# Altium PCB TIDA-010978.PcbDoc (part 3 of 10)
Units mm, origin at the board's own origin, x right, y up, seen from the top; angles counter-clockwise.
Board outline 243.95 x 94.85 mm, 4 copper layers (Top Layer, Mid Layer 1, Mid Layer 2, Bottom Layer), stack 1.623 mm thick; 865 components, 374 nets, 2308 pads, 2132 vias.
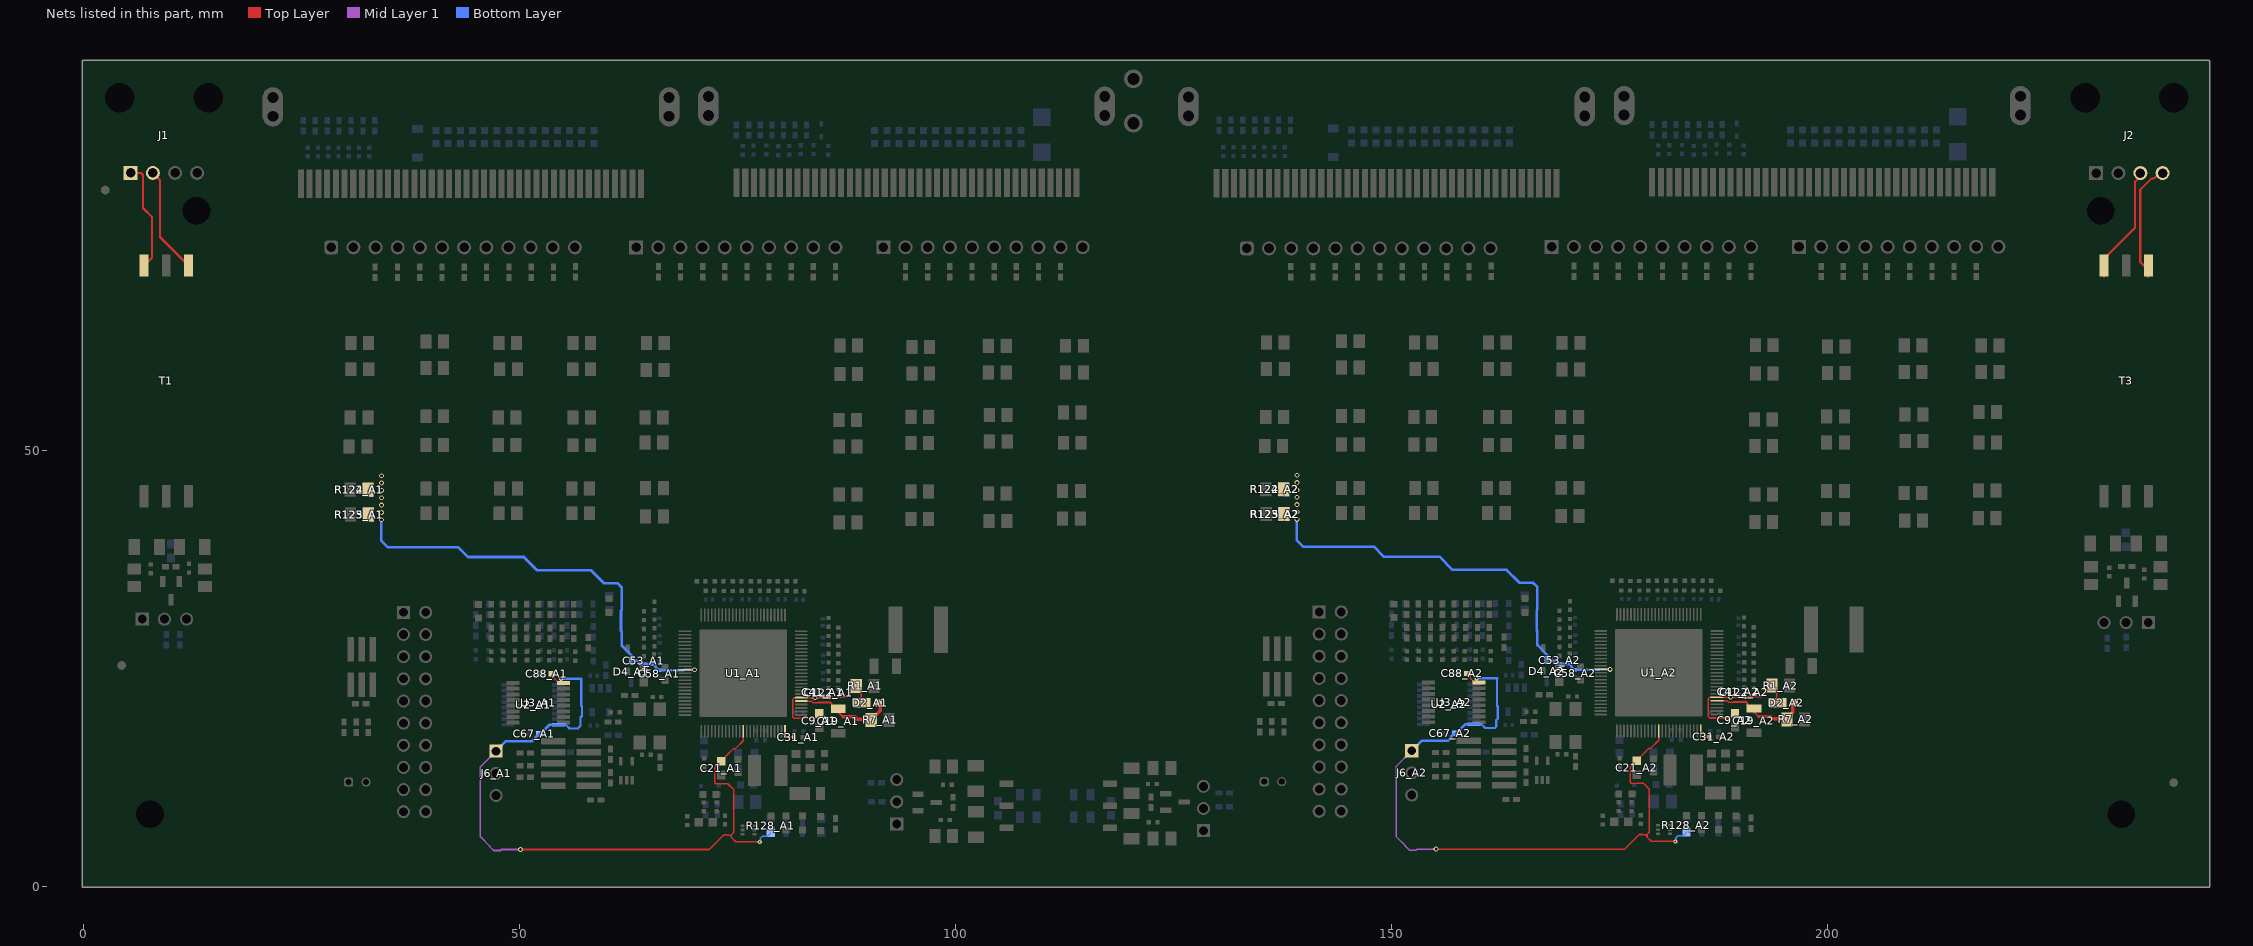
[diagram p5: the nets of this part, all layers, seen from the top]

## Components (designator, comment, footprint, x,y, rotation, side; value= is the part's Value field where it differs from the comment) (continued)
T2 "74941301" FP-HMU1228NL_SMT_TRANSFORMER_8MM89_10MM09-MFG 111.8,9.242 r0 top
T3 "LKBMT10B" FP-LKBMT10B_SMT_XFRMR_27MM9_12MM5-MFG 234.256,57.975 r270 top
TSREF_LED1_A1 "150060GS75000" WL-SMCW_GREEN 60.292,32.184 r270 top value=Green (schematic designator TSREF_LED1)
TSREF_LED1_A2 "150060GS75000" WL-SMCW_GREEN 165.293,32.234 r270 top value=Green (schematic designator TSREF_LED1)
U1_A1 "BQ79826ZQPZSRQ1" PZQ0100A-MFG 75.657,24.449 r180 top (schematic designator U1)
U1_A2 "BQ79826ZQPZSRQ1" PZQ0100A-MFG 180.657,24.499 r180 top (schematic designator U1)
U2_A1 "TMUX1308PWR" PW0016A-MFG 51.573,20.814 r0 bottom (schematic designator U2)
U2_A2 "TMUX1308PWR" PW0016A-MFG 156.573,20.864 r0 bottom (schematic designator U2)
U3_A1 "TMUX1308PWR" PW0016A-MFG 52.143,21.049 r0 top (schematic designator U3)
U3_A2 "TMUX1308PWR" PW0016A-MFG 157.143,21.099 r0 top (schematic designator U3)
U4_A1 "TLV74315PDBVR" DBV0005A_N 59.3,21.342 r270 bottom (schematic designator U4)
U4_A2 "TLV74315PDBVR" DBV0005A_N 164.3,21.392 r270 bottom (schematic designator U4)
U5_A1 "SN74LXC1T14DCKR" DCK0005A-MFG 62.287,13.257 r90 top (schematic designator U5)
U5_A2 "SN74LXC1T14DCKR" DCK0005A-MFG 167.287,13.307 r90 top (schematic designator U5)
Y2_A1 "830055663" FP-830055663_SMT_CRYSTAL_5MM0_3MM2-MFG 64.944,18.413 r90 top (schematic designator Y2)
Y2_A2 "830055663" FP-830055663_SMT_CRYSTAL_5MM0_3MM2-MFG 169.944,18.463 r90 top (schematic designator Y2)
ZZ1 "This Assembly Note is for PCB labels only" AssemblyNoteLabel 32.749,188.65 r0 top
ZZ2 "These assemblies are ESD sensitive, ESD precautions shall be observed." AssemblyNote 32.749,185.884 r0 top
ZZ3 "These assemblies must be clean and free from flux and all contaminants. Use of no clean flux is not acceptable." AssemblyNote 32.749,183.635 r0 top
ZZ4 "These assemblies must comply with workmanship standards IPC-A-610 Class 2, unless otherwise specified." AssemblyNote 32.749,181.386 r0 top

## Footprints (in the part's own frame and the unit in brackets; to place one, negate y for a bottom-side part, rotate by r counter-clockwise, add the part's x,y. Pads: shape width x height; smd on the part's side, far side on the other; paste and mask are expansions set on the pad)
0402 [mm] "0402 from SM-752 data"
  rect 0.8x0.6 smd: 1(-0.6,0) 2(0.6,0)
  silkscreen extent -1.22,-0.52 1.22,0.52, body extent -0.55,-0.3 0.55,0.3, height 0.6
0603 [mm] "0603 from SM-752 data"
  rect 1x0.95 smd: 1(-0.8,0) 2(0.8,0)
  silkscreen extent -1.52,-0.69 1.52,0.69, body extent -0.87,-0.47 0.87,0.47, height 1
0805_HV [mil] "0805 with 30mil clearance between pads"
  rect 50x63 smd: 1(-40,0) 2(40,0)
  silkscreen extent -74,-40 74,40, body extent -43,-29 43,29, height 57
1206 [mm] "1206 from SM-752 data"
  rect 1.3x1.85 smd: 1(-1.45,0) 2(1.45,0)
  silkscreen extent -2.4,-1.21 2.4,1.21, body extent -1.7,-0.9 1.7,0.9, height 1.35
2220_280 [mm] "Chip Capacitor, Body 5.7x5.0mm, IPC Medium Density"
  rect 1.6x5.3 smd: 1(-2.6,0) 2(2.6,0)
  silkscreen extent -3.69,-2.94 3.69,2.94, body extent -2.95,-2.62 2.95,2.62, height 2.8
61301211121 [mm] "Pin Header, pitch 2.54 mm, THT, Vertical, single row, 12p"
  rrect50% 1.6x1.6 hole 1.1: 1(-13.97,0)
  round 1.6 hole 1.1: 2(-11.43,0) 3(-8.89,0) 4(-6.35,0) 5(-3.81,0) 6(-1.27,0) 7(1.27,0) 8(3.81,0) 9(6.35,0) 10(8.89,0) 11(11.43,0) 12(13.97,0)
  silkscreen extent -15.96,-1.35 15.39,1.35, body extent -15.24,-1.27 15.24,1.27, height 8.57
AssemblyNote [mm] "Assembly Note"
AssemblyNoteLabel [mm] "Assembly Note for PCB Labels"
CE_Mark_5mm [mm] "Minimum text height for CE Mark"
  silkscreen extent -3.5,-2.5 3.5,2.5
CONN_PEC03SAAN [mm] "SULLINS"
  rect 1.5x1.5 hole 1.016: 1(-2.54,0)
  round 1.5 hole 1.016: 2(0,0) 3(2.54,0)
  silkscreen extent -4.72,-1.27 3.81,1.27, body extent -3.84,-1.3 3.84,1.3, height 8.38
DBV0005A_N [mm] "SOT23, 5-Leads, Body 2.9x1.6mm, Pitch 0.95mm, Lead Span 2.8mm, IPC Medium Density"
  rrect17% 1x0.6 smd: 1(-1.375,0.95) 2(-1.375,0) 3(-1.375,-0.95) 4(1.375,-0.95) 5(1.375,0.95)
  silkscreen extent -0.25,-1.55 0.25,1.55, body extent -1.42,-1.46 1.42,1.46, height 1.09
DBZ0003A-MFG [mm]
  rrect17% 1.3x0.6 smd paste+0 mask+0: 1(-1.05,0.95) 2(-1.05,-0.95) 3(1.05,0)
  silkscreen extent -0.03,-1.52 0.7,1.52, body extent -1.8,-1.62 1.8,1.62, height 0.25
DCK0005A-MFG [mm]
  rrect25% 0.95x0.4 smd paste+0 mask+0: 1(-1.1,0.65) 2(-1.1,0) 3(-1.1,-0.65) 4(1.1,-0.65) 5(1.1,0.65)
  silkscreen extent -2.25,-1.07 0.23,1.07, body extent -1.68,-1.17 1.68,1.17, height 0.25
DYA0002A-MFG [mm]
  rrect25% 0.67x0.4 smd paste+0 mask+0: 1(-0.74,0) 2(0.74,0)
  silkscreen extent -1.75,-0.63 0.65,0.63, body extent -0.8,-0.39 0.8,0.39, height 0.77
DYF0002A-MFG [mm] "Recommended Land Pattern"
  rrect20% 0.9x0.5 smd paste+0 mask+0: 1(-1.3,0) 2(1.3,0)
  silkscreen extent -1.55,-0.7 0.9,0.92, body extent -1.33,-0.65 1.33,0.65, height 1
FCC_disclaimer [mm]
Fiducial10-20 [mm]
  round 1 smd mask+0.5: 1(0,0)
  Top Layer keep-out circle w1.178: c0,0 r0.5
FP-63824-1_CONN_7MM92_3MM11-MFG [mm]
  round 2.15 hole 1.4 paste-2539.97 mask+0: 1(-2.54,0) 1(2.54,0)
  silkscreen extent -4.09,-1.56 4.09,1.56, body extent -3.96,-1.54 3.96,1.54, height 10.88
FP-141114-214010_HDR40-MFG [mm]
  rrect14% 0.7x3.3 smd paste+0 mask+0: 1(18.5,7.7) 2(16.5,7.7) 3(14.5,7.7) 4(12.5,7.7) 5(10.5,7.7) 6(8.5,7.7) 7(6.5,7.7) 8(4.5,7.7) 9(2.5,7.7) 10(0.5,7.7) 11(-1.5,7.7) 12(-3.5,7.7) 13(-5.5,7.7) 14(-7.5,7.7) 15(-9.5,7.7) 16(-11.5,7.7) 17(-13.5,7.7) 18(-15.5,7.7) 19(-17.5,7.7) 20(-19.5,7.7) 21(19.5,7.7) 22(17.5,7.7) 23(15.5,7.7) 24(13.5,7.7) 25(11.5,7.7) 26(9.5,7.7) 27(7.5,7.7) 28(5.5,7.7) 29(3.5,7.7) 30(1.5,7.7) 31(-0.5,7.7) 32(-2.5,7.7) 33(-4.5,7.7) 34(-6.5,7.7) 35(-8.5,7.7) 36(-10.5,7.7) 37(-12.5,7.7) 38(-14.5,7.7) 39(-16.5,7.7) 40(-18.5,7.7)
  round 2.35 hole 1.25 paste-2539.97 mask+0: 41(-22.725,-2.175) 41(-22.725,-0.025) 42(22.725,-2.175) 42(22.725,-0.025)
  rrect100% 2.35x4.5 smd paste+0 mask+0: 41(-22.725,-1.1) 42(22.725,-1.1)
  rrect100% 2.35x4.5 smd far side paste+0 mask+0: 41(-22.725,-1.1) 42(22.725,-1.1)
  silkscreen extent -23.95,1.83 23.95,10.02, body extent -24.05,-9.3 24.05,9.45, height 0.25
FP-830055663_SMT_CRYSTAL_5MM0_3MM2-MFG [mm]
  rrect7% 1.6x1.4 smd paste+0 mask+0: 1(-1.9,-1.15) 2(1.9,-1.15) 3(1.9,1.15) 4(-1.9,1.15)
  silkscreen extent -2.55,-2.53 2.55,1.65, body extent -2.5,-1.6 2.5,1.6, height 1
FP-885012206050_0603-MFG [mm]
  rrect13% 0.8x0.8 smd paste+0 mask+0: 1(-0.75,0) 2(0.75,0)
  silkscreen extent -0.85,-0.77 0.85,0.77, body extent -0.8,-0.4 0.8,0.4, height 0.87
FP-C1206C-EB-MFG [mm]
  rect 0.95x1.7 smd paste+0 mask+0: 1(-1.4,0) 2(1.4,0)
  silkscreen extent -0.55,-0.9 0.55,0.9, body extent -2,-1 2,1, height 0.25
FP-CRCW120662R0JNEAHP_1206-MFG [mm] "Recommended Land Pattern"
  rrect10% 1.05x1.8 smd paste+0 mask+0: 1(-1.275,0) 2(1.275,0)
  silkscreen extent -0.38,-0.87 0.38,0.87, body extent -1.55,-0.8 1.55,0.8, height 0.65
FP-DFLS1200Q-7_PowerDI123-MFG [mm]
  rrect7% 2.4x1.5 smd paste+0 mask+0: 1(0.85,0)
  rrect10% 1.05x1.5 smd paste+0 mask+0: 2(-1.525,0)
  silkscreen extent -1.5,-1.25 2.8,1.25, body extent -2.15,-1.06 2.15,1.06, height 0.25
FP-ERJ-2RKF10R0X_0402-MFG [mm]
  rrect21% 0.475x0.5 smd paste+0 mask+0: 1(-0.513,0) 2(0.513,0)
  silkscreen extent -0.53,-0.63 0.53,0.63, body extent -0.85,-0.38 0.85,0.38, height 0.25
FP-FTSH-103-01-F-DV-TR_HDR6-MFG [mm]
  rrect14% 0.74x2.79 smd paste+0 mask+0: 1(-1.27,-2.035) 2(-1.27,2.035) 3(0,-2.035) 4(0,2.035) 5(1.27,-2.035) 6(1.27,2.035)
  silkscreen extent -1.97,-4.26 1.97,0.27, body extent -2.07,-3.53 2.07,3.53, height 0.25
FP-GRM155C81C105KE11D_0402-MFG [mm]
  rrect25% 0.4x0.5 smd paste+0 mask+0: 1(-0.4,0) 2(0.4,0)
  silkscreen extent -0.53,-0.65 0.53,0.65, body extent -0.5,-0.25 0.5,0.25, height 0.6
FP-HMU1228NL_SMT_TRANSFORMER_8MM89_10MM09-MFG [mm]
  rrect13% 1.585x0.76 smd paste+0 mask+0: 1(-5.937,2.54) 2(-5.937,0) 3(-5.937,-2.54) 4(5.937,-2.54) 5(5.937,0) 6(5.937,2.54)
  silkscreen extent -7.5,-4.51 5.08,4.51, body extent -6.83,-4.61 6.83,4.61, height 0.25
FP-LKBMT10B_SMT_XFRMR_27MM9_12MM5-MFG [mm]
  rrect10% 2.55x1.02 smd paste+0 mask+0: 1(-13.225,2.54) 2(-13.225,0) 3(-13.225,-2.54) 4(13.225,-2.54) 5(13.225,0) 6(13.225,2.54)
  silkscreen extent -15.17,-6.38 14.08,6.38, body extent -15.85,-6.48 15.85,6.48, height 0.25
FP-MSP3V3-M3/89A_DO-219AD-MFG [mm] "Recommended Land Pattern"
  rrect9% 2x1.1 smd paste+0 mask+0: 1(-0.65,0)
  rrect13% 0.8x0.8 smd paste+0 mask+0: 2(1.25,0)
  silkscreen extent -2.32,-0.92 1.15,0.92, body extent -1.75,-0.8 1.75,0.8, height 0.25
FP-SMD16PL-TP_SOD123FL-MFG [mm]
  rrect11% 0.91x1.22 smd paste+0 mask+0: 1(-1.635,0) 2(1.635,0)
  silkscreen extent -2.82,-0.95 0.35,0.95, body extent -1.79,-0.82 1.79,0.82, height 1.35
FP-SSM6L56FE,LM_SOT563-MFG [mm]
  rrect33% 0.3x0.45 smd paste+0 mask+0: 1(-0.5,-0.675) 2(0,-0.675) 3(0.5,-0.675) 4(0.5,0.675) 5(0,0.675) 6(-0.5,0.675)
  silkscreen extent -0.82,-1.57 0.82,0.08, body extent -0.92,-1 0.92,1, height 0.25
IEC_HighVoltage_Small [mm]
  silkscreen extent -2.72,-2.24 2.72,2.47
JST_B2B-PH-K-S [mm] "Header(shrouded), 2mm, 2x1, TH"
  rrect50% 1.05x1.05 hole 0.7: 1(-1,0.55)
  round 1.05 hole 0.7: 2(1,0.55)
  body extent -2.95,-2.25 2.95,2.25, height 6
Label_650x200 [mil] "Thermal Transfer Label"
  round 1 on Mech13: 0(0,0)
  silkscreen extent -325,-100 325,100, body extent -325,-100 325,100, height 1
Molex_70551-0038 [mm] "Header(shrouded), 2.54mm, 4x1, R/A, TH"
  rect 1.6x1.6 hole 1.09: 1(0,3.81)
  round 1.6 hole 1.09: 2(0,1.27) 3(0,-1.27) 4(0,-3.81)
  round 0 hole 3.4 unplated paste-2539.97 mask+0: MH1(8.64,-5.08) MH2(8.64,5.08)
  silkscreen extent 1.45,-6.98 12.88,7.32, body extent -0.71,-6.98 12.88,6.98, height 6.6
NPTH125mil [mil]
  round 120 hole 125 unplated mask+15: 1(0,0)
PW0016A-MFG [mm]
  rrect22% 1.5x0.45 smd paste+0 mask+0: 1(-2.9,2.275) 2(-2.9,1.625) 3(-2.9,0.975) 4(-2.9,0.325) 5(-2.9,-0.325) 6(-2.9,-0.975) 7(-2.9,-1.625) 8(-2.9,-2.275) 9(2.9,-2.275) 10(2.9,-1.625) 11(2.9,-0.975) 12(2.9,-0.325) 13(2.9,0.325) 14(2.9,0.975) 15(2.9,1.625) 16(2.9,2.275)
  silkscreen extent -4.32,-2.55 1.78,2.55, body extent -3.2,-2.5 3.2,2.5, height 1.2
PZQ0100A-MFG [mm]
  rrect50% 1.45x0.2 smd paste+0 mask+0: 1(-6.675,4.8) 2(-6.675,4.4) 3(-6.675,4) 4(-6.675,3.6) 5(-6.675,3.2) 6(-6.675,2.8) 7(-6.675,2.4) 8(-6.675,2) 9(-6.675,1.6) 10(-6.675,1.2) 11(-6.675,0.8) 12(-6.675,0.4) 13(-6.675,0) 14(-6.675,-0.4) 15(-6.675,-0.8) 16(-6.675,-1.2) 17(-6.675,-1.6) 18(-6.675,-2) 19(-6.675,-2.4) 20(-6.675,-2.8) 21(-6.675,-3.2) 22(-6.675,-3.6) 23(-6.675,-4) 24(-6.675,-4.4) 25(-6.675,-4.8) 51(6.675,-4.8) 52(6.675,-4.4) 53(6.675,-4) 54(6.675,-3.6) 55(6.675,-3.2) 56(6.675,-2.8) 57(6.675,-2.4) 58(6.675,-2) 59(6.675,-1.6) 60(6.675,-1.2) 61(6.675,-0.8) 62(6.675,-0.4) 63(6.675,0) 64(6.675,0.4) 65(6.675,0.8) 66(6.675,1.2) 67(6.675,1.6) 68(6.675,2) 69(6.675,2.4) 70(6.675,2.8) 71(6.675,3.2) 72(6.675,3.6) 73(6.675,4) 74(6.675,4.4) 75(6.675,4.8)
  rrect50% 0.2x1.45 smd paste+0 mask+0: 26(-4.8,-6.675) 27(-4.4,-6.675) 28(-4,-6.675) 29(-3.6,-6.675) 30(-3.2,-6.675) 31(-2.8,-6.675) 32(-2.4,-6.675) 33(-2,-6.675) 34(-1.6,-6.675) 35(-1.2,-6.675) 36(-0.8,-6.675) 37(-0.4,-6.675) 38(0,-6.675) 39(0.4,-6.675) 40(0.8,-6.675) 41(1.2,-6.675) 42(1.6,-6.675) 43(2,-6.675) 44(2.4,-6.675) 45(2.8,-6.675) 46(3.2,-6.675) 47(3.6,-6.675) 48(4,-6.675) 49(4.4,-6.675) 50(4.8,-6.675) 76(4.8,6.675) 77(4.4,6.675) 78(4,6.675) 79(3.6,6.675) 80(3.2,6.675) 81(2.8,6.675) 82(2.4,6.675) 83(2,6.675) 84(1.6,6.675) 85(1.2,6.675) 86(0.8,6.675) 87(0.4,6.675) 88(0,6.675) 89(-0.4,6.675) 90(-0.8,6.675) 91(-1.2,6.675) 92(-1.6,6.675) 93(-2,6.675) 94(-2.4,6.675) 95(-2.8,6.675) 96(-3.2,6.675) 97(-3.6,6.675) 98(-4,6.675) 99(-4.4,6.675) 100(-4.8,6.675)
  rrect1% 10x10 smd paste-1000 mask-1000: 101(0,0)
  silkscreen extent -6.88,-6.05 6.05,6.05, body extent -7.5,-7.5 7.5,7.5, height 0.25
Samtec_FTSH-105-01-x-DV-K [mm] "Header(Shrouded), 1.27mm, 5x2, SMT"
  rect 2.79x0.74 smd: 1(-2.035,2.54) 2(2.035,2.54) 3(-2.035,1.27) 4(2.035,1.27) 5(-2.035,0) 6(2.035,0) 7(-2.035,-1.27) 8(2.035,-1.27) 9(-2.035,-2.54) 10(2.035,-2.54)
  silkscreen extent -3.73,-3.48 3.73,3.48, body extent -2.92,-3.18 2.92,3.17, height 6.13
SMA [mm] "Molded Diode, 2-Leads, Body 4.3x2.6mm, IPC Medium Density, based on OnSemi component dimensions and land pattern"
  rect 2x2 smd: 1(-2,0) 2(2,0)
  silkscreen extent -3.66,-1.57 2.79,1.57, body extent -2.6,-1.3 2.6,1.3, height 2.42
Sullins_xxxC010DAAN [mm] "Header, 2.54mm, 10x2, TH"
  rect 1.5x1.5 hole 1: 1(-1.27,11.43)
  round 1.5 hole 1: 2(1.27,11.43) 3(-1.27,8.89) 4(1.27,8.89) 5(-1.27,6.35) 6(1.27,6.35) 7(-1.27,3.81) 8(1.27,3.81) 9(-1.27,1.27) 10(1.27,1.27) 11(-1.27,-1.27) 12(1.27,-1.27) 13(-1.27,-3.81) 14(1.27,-3.81) 15(-1.27,-6.35) 16(1.27,-6.35) 17(-1.27,-8.89) 18(1.27,-8.89) 19(-1.27,-11.43) 20(1.27,-11.43)
  silkscreen extent -2.5,-12.7 2.5,13.14, body extent -2.5,-12.7 2.5,12.7, height 8.34
TI_Stacked_Overlay_Small [mm]
  silkscreen extent -10.63,-2.49 10.63,2.49
WCAP-CSGP_0402_L1W0.5H0.5 [mm] "Ceramic Capacitors, body 1x0.5mm"
  rect 0.5x0.5 smd: 1(-0.5,0) 2(0.5,0)
  body extent -0.5,-0.25 0.5,0.25, height 0.5
WCAP-CSGP_0603_L1.6W0.8H0.8_Reflow [mm] "Ceramic Capacitors, body 1.6x0.8mm"
  rect 0.8x0.8 smd: 1(-0.75,0) 2(0.75,0)
  body extent -0.8,-0.4 0.8,0.4, height 0.8
WCAP-CSGP_0805_L2W1.25H1.25 [mm] "Ceramic Capacitors, body 2x1.25mm"
  rect 0.9x1.3 smd: 1(-0.95,0) 2(0.95,0)
  body extent -1,-0.63 1,0.63, height 1.25
WCAP-CSMH_0603_L1.6W0.8H0.8_Reflow [mm] "Ceramic Capacitors, body 1.6x0.8mm"
  rect 0.8x0.8 smd: 1(-0.75,0) 2(0.75,0)
  body extent -0.8,-0.4 0.8,0.4, height 0.8
WCAP-CSMH_0805_L2W1.25H1.25 [mm] "Ceramic Capacitors, body 2x1.25mm"
  rect 0.9x1.3 smd: 1(-0.95,0) 2(0.95,0)
  body extent -1,-0.63 1,0.63, height 1.25
WE-LQS_4018 [mm] "SMD Power Inductor, 2-Leads, body 4x4mm"
  rect 1.5x3.6 smd: 1(-1.525,0) 2(1.525,0)
  silkscreen extent -2.1,-2.1 2.1,2.1, body extent -2,-2 2,2, height 1.8
WEEE_Minimum [mm] "WEEElie bin"
  silkscreen extent -2.42,-4.38 2.52,2.65
WL-SMCW_GREEN [mm] "WURTH"
  rect 0.8x0.8 smd: 1(-0.8,0) 2(0.8,0)
  silkscreen extent -1.9,-0.8 1.2,0.8, body extent -0.85,-0.45 0.85,0.45, height 0.8
WL-SMCW_RED [mm] "WURTH"
  rect 0.8x0.8 smd: 1(-0.8,0) 2(0.8,0)
  silkscreen extent -1.9,-0.8 1.2,0.8, body extent -0.85,-0.45 0.85,0.45, height 0.8
Wurth_61301011121 [mm] "Header, 2.54mm, 10x1, TH"
  rect 1.6x1.6 hole 1.1: 1(-11.43,0)
  round 1.6 hole 1.1: 2(-8.89,0) 3(-6.35,0) 4(-3.81,0) 5(-1.27,0) 6(1.27,0) 7(3.81,0) 8(6.35,0) 9(8.89,0) 10(11.43,0)
  silkscreen extent -12.7,-1.27 12.7,1.6, body extent -12.7,-1.27 12.7,1.27, height 8.54

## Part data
AVDD_LED1_A1 AVDD_LED1_A2 DVDD_LED1_A1 DVDD_LED1_A2 LDOIN_LED1_A1 LDOIN_LED1_A2 TSREF_LED1_A1 TSREF_LED1_A2: library part CMP-0002905-2, "LED, Green, SMD", Color=Green, Manufacturer="Wurth Elektronik", Value1=W, Value2=3.2V
C1 C2 C6 C7: library part CMP-03913-89205736-1, "885342207006 Cap Cer 0.022UF 200V X7R 0805", Capacitance=22nF, Dielectric=X7R, Insulation Resistance=4.545GΩ, Max Operating Temperature=125°C, Min Operating Temperature=-55°C, Voltage Rating=200V
C3 C4 C5 C8: library part CMP-0750041-1, "CAP, CERM, 100 pF, 50 V,+/- 5%, C0G/NP0, AEC-Q200 Grade 1, 0603", Cap_Case=0603, Manufacturer=MuRata, TempCo=C0G/NP0, Tolerance_%=5%, Value2=50V, ValueDisplayed=100pF
C9_A1 C9_A2: library part CMP-0006852-4, "CAP, CERM, 0.01 uF, 200 V, +/- 10%, X7R, 0603", Cap_Case=0603, Manufacturer=Kemet, Supplier Part Number 1=399-5088-1-ND, TempCo=X7R, Tolerance_%=10%, Value1=Unknown, Value2=200V, ValueDisplayed=0.01uF
C10_A1 C10_A2: library part CMP-0085301-1, "CAP, CERM, 1 µF, 250 V,+/- 10%, X7R, AEC-Q200 Grade 1, 2220", Cap_Case=2220, Manufacturer=TDK, TempCo=X7R, Tolerance_%=10%, Value2=250V, ValueDisplayed=1µF
C11_A1 C11_A2 C22_A1 C22_A2 C30_A1 C30_A2: library part CMP-0097608-1, "0.47 µF ±10% 16V Ceramic Capacitor X7R 0603 (1608 Metric)", Digikey Part Number=732-7969-1-ND, Manufacturer="Wurth Electronics", Mouser Part Number=710-885012206050, Operating Temperature Range="-55°C to +125°C", TempCo=15%, Temperature Characteristic=X7R, Tolerance_%=10%, ValueDisplayed=470nF
C12_A1 C12_A2 C13_A1 C13_A2 C14_A1 C14_A2 C15_A1 C15_A2 C25_A1 C25_A2 C26_A1 C26_A2 C27_A1 C27_A2 C28_A1 C28_A2 C34_A1 C34_A2 C35_A1 C35_A2 C36_A1 C36_A2 C37_A1 C37_A2 C41_A1 C41_A2 C42_A1 C42_A2 C43_A1 C43_A2 C44_A1 C44_A2 C45_A1 C45_A2 C46_A1 C46_A2 C47_A1 C47_A2 C48_A1 C48_A2 C49_A1 C49_A2 C50_A1 C50_A2 C53_A1 C53_A2 C54_A1 C54_A2 C55_A1 C55_A2 C56_A1 C56_A2 C57_A1 C57_A2 C58_A1 C58_A2 C158_A1 C158_A2 C159_A1 C159_A2: library part CMP-0094775-1, "Chip Multilayer Ceramic Capacitors for General Purpose, 0402, 1.0uF, X6S, 22%, 10%, 16V", Manufacturer=Murata, Operating Temperature Range="-55°C to +105°C", TempCo=22%, Temperature Characteristic=X6S, Tolerance_%=10%, ValueDisplayed=1.0uF
C16_A1 C16_A2 C17_A1 C17_A2: library part CMP-03913-65419739-1, "885012107014 Ceramic Capacitor, Multilayer, Ceramic, 16V, 20% +Tol, 20% -Tol, X5R, 15% TC, 10uF, Surface Mount, 0805", Capacitance=10µF, Case Code (Imperial)=0805, Case Code (Metric)=2012, Dielectric=X5R, Insulation Resistance=10MΩ, Max Operating Temperature=85°C, Min Operating Temperature=-55°C, Tolerance=20%, Voltage Rating=16V
C18_A1 C18_A2: library part CMP-0007965-2, "CAP, CERM, 10 uF, 16 V, +/- 10%, X7S, AEC-Q200 Grade 1, 0805", Cap_Case=0805, Manufacturer=TDK, PartNumber=CGA4J1X7S1C106K125AC, Supplier Part Number 1=445-16110-1-ND, TempCo=X7S, Tolerance_%=10%, Value1=Unknown, Value2=16V, ValueDisplayed=10uF
C19_A1 C19_A2: library part CMP-03020-023125-1, "C1206 0.15 μF X7R 10.00% 250 V", Capacitance="0.15 μF", Manufacturer=KEMET, Package=C1206C-EB, Temperature="-55°C to +150°C", Temperature Characteristic=X7R, Temperature Coefficient=15%, Temperature Range High=+150°C, Temperature Range Low=-55°C, Tolerance=0.1, Voltage Rating="250 V"
C20_A1 C20_A2: library part CMP-0115820-1, "WCAP-CSMH Multilayer Ceramic Chip Capacitor, Mid and High Voltage, size 0603, NP0 Class I, 220pF, 250VDC", Capacitance Tolerance=5%, Case/Size Code=0603, Insulation Resistance=10GOhm, Manufacturer="Wurth Elektronik", Manufacturer Part Number=885342006004, Operating Temperature Max=125°C, Operating Temperature Min=-55°C, Rated Voltage (DC)=250V
C21_A1 C21_A2 C23_A1 C23_A2: library part CMP-0006833-4, "CAP, CERM, 1 uF, 25 V, +/- 10%, X7R, 0603", Cap_Case=0603, Manufacturer="Wurth Elektronik", Supplier Part Number 1=732-7994-1-ND, TempCo=X7R, Tolerance_%=10%, Value1=Unknown, Value2=25V, ValueDisplayed=1uF
C24_A1 C24_A2: library part CMP-0119395-1, "WCAP-CSGP Multilayer Ceramic Chip Capacitor, General Purpose, size 0603, X7R, 10nF, 50VDC", Capacitance Tolerance=+/-10%, Case/Size Code=0603, Insulation Resistance=10GOhm, Manufacturer="Wurth Elektronik", Operating Temperature Max=125°C, Operating Temperature Min=-55°C, Rated Voltage (DC)=50V
C29_A1 C29_A2 C33_A1 C33_A2 C40_A1 C40_A2 C51_A1 C51_A2 C52_A1 C52_A2 C155_A1 C155_A2: library part CMP-03913-130590226-1, "885012205092 Cap, 0.1Uf, 50V, Mlcc, 0402 Rohs Compliant: Yes", Capacitance=100nF, Insulation Resistance=500MΩ, Max Operating Temperature=125°C, Min Operating Temperature=-55°C, Voltage Rating=50V
C31_A1 C31_A2: library part CMP-0119297-1, "WCAP-CSGP Multilayer Ceramic Chip Capacitor, General Purpose, size 0402, X7R, 10nF, 50VDC", Capacitance Tolerance=+/-10%, Case/Size Code=0402, Insulation Resistance=10GOhm, Manufacturer="Wurth Elektronik", Operating Temperature Max=125°C, Operating Temperature Min=-55°C, Rated Voltage (DC)=50V
C32_A1 C32_A2: library part CMP-0006467-2, "CAP, CERM, 47 pF, 50 V, +/- 1%, C0G/NP0, 0402", Cap_Case=0402, Manufacturer=MuRata, PartNumber=GRM1555C1H470FA01D, Supplier Part Number 1=490-6241-1-ND, TempCo=C0G/NP0, Tolerance_%=1%, Value1=Unknown, Value2=50V, ValueDisplayed=47pF
C38_A1 C38_A2: library part CMP-0119376-1, "WCAP-CSGP Multilayer Ceramic Chip Capacitor, General Purpose, size 0603, X7R, 150nF, 25VDC", Capacitance Tolerance=+/-10%, Case/Size Code=0603, Insulation Resistance=3.3GOhm, Manufacturer="Wurth Elektronik", Operating Temperature Max=125°C, Operating Temperature Min=-55°C, Rated Voltage (DC)=25V
C39_A1 C39_A2: library part CMP-0007136-5, "CAP, CERM, 1 uF, 16 V, +/- 10%, X7R, AEC-Q200 Grade 1, 0603", Cap_Case=0603, Manufacturer=MuRata, PartNumber=GCM188R71C105KA64D, Supplier Part Number 1=490-5241-6-ND, TempCo=X7R, Tolerance_%=10%, Value1=Unknown, Value2=16V, ValueDisplayed=1uF
C59_A1 C59_A2 C60_A1 C60_A2 C61_A1 C61_A2 C62_A1 C62_A2 C63_A1 C63_A2 C64_A1 C64_A2 C65_A1 C65_A2 C66_A1 C66_A2 C68_A1 C68_A2 C69_A1 C69_A2 C72_A1 C72_A2 C73_A1 C73_A2 C76_A1 C76_A2 C77_A1 C77_A2 C80_A1 C80_A2 C81_A1 C81_A2: library part CMP-0119302-1, "WCAP-CSGP Multilayer Ceramic Chip Capacitor, General Purpose, size 0402, X7R, 100nF, 50VDC", Capacitance Tolerance=+/-10%, Case/Size Code=0402, Insulation Resistance=0.5GOhm, Manufacturer="Wurth Elektronik", Operating Temperature Max=125°C, Operating Temperature Min=-55°C, Rated Voltage (DC)=50V
C67_A1 C67_A2 C88_A1 C88_A2 C94_A1 C94_A2 C142_A1 C142_A2 C143_A1 C143_A2 C160_A1 C160_A2 C161_A1 C161_A2: library part CMP-0006356-2, "CAP, CERM, 0.1 uF, 50 V, +/- 10%, X7R, AEC-Q200 Grade 1, 0402", Cap_Case=0402, Manufacturer=MuRata, Supplier Part Number 1=490-10672-1-ND, TempCo=X7R, Tolerance_%=10%, Value1=Unknown, Value2=50V, ValueDisplayed=0.1uF
C70_A1 C70_A2 C71_A1 C71_A2 C75_A1 C75_A2 C79_A1 C79_A2 C83_A1 C83_A2 C85_A1 C85_A2 C87_A1 C87_A2 C90_A1 C90_A2 C93_A1 C93_A2 C96_A1 C96_A2 C99_A1 C99_A2 C103_A1 C103_A2 C105_A1 C105_A2 C109_A1 C109_A2 C113_A1 C113_A2 C115_A1 C115_A2 C119_A1 C119_A2 C123_A1 C123_A2 C125_A1 C125_A2 C129_A1 C129_A2 C132_A1 C132_A2 C133_A1 C133_A2 C134_A1 C134_A2 C135_A1 C135_A2 C140_A1 C140_A2 C141_A1 C141_A2 C146_A1 C146_A2: library part CMP-0119785-1, "WCAP-CSMH Multilayer Ceramic Chip Capacitor, Mid and High Voltage, size 0603, X7R Class II, 10nF, 250VDC", Capacitance Tolerance=10%, Case/Size Code=0603, Insulation Resistance=10GOhm, Manufacturer="Wurth Elektronik", Operating Temperature Max=125°C, Operating Temperature Min=-55°C, Rated Voltage (DC)=250V
C74_A1 C74_A2 C78_A1 C78_A2 C82_A1 C82_A2 C84_A1 C84_A2 C86_A1 C86_A2 C89_A1 C89_A2 C92_A1 C92_A2 C95_A1 C95_A2 C98_A1 C98_A2 C102_A1 C102_A2 C104_A1 C104_A2 C108_A1 C108_A2 C112_A1 C112_A2 C114_A1 C114_A2 C118_A1 C118_A2: library part CMP-0119301-1, "WCAP-CSGP Multilayer Ceramic Chip Capacitor, General Purpose, size 0402, X7R, 100nF, 25VDC", Capacitance Tolerance=+/-10%, Case/Size Code=0402, Insulation Resistance=5GOhm, Manufacturer="Wurth Elektronik", Operating Temperature Max=125°C, Operating Temperature Min=-55°C, Rated Voltage (DC)=25V
C91_A1 C91_A2 C97_A1 C97_A2 C100_A1 C100_A2 C101_A1 C101_A2 C106_A1 C106_A2 C107_A1 C107_A2 C110_A1 C110_A2 C111_A1 C111_A2 C116_A1 C116_A2 C117_A1 C117_A2 C120_A1 C120_A2 C121_A1 C121_A2 C122_A1 C122_A2 C126_A1 C126_A2 C127_A1 C127_A2 C130_A1 C130_A2 C131_A1 C131_A2 C136_A1 C136_A2 C137_A1 C137_A2 C144_A1 C144_A2 C145_A1 C145_A2 C152_A1 C152_A2 C153_A1 C153_A2 C156_A1 C156_A2 C157_A1 C157_A2 C162_A1 C162_A2 C163_A1 C163_A2 C164_A1 C164_A2: library part CMP-0119292-1, "WCAP-CSGP Multilayer Ceramic Chip Capacitor, General Purpose, size 0402, X7R, 1.5nF, 50VDC", Capacitance Tolerance=+/-10%, Case/Size Code=0402, Insulation Resistance=10GOhm, Manufacturer="Wurth Elektronik", Operating Temperature Max=125°C, Operating Temperature Min=-55°C, Rated Voltage (DC)=50V
C124_A1 C124_A2 C128_A1 C128_A2: library part CMP-0118817-1, "WCAP-CSGP Multilayer Ceramic Chip Capacitor, General Purpose, size 0402, NP0, 22pF, 50VDC", Capacitance Tolerance=+/-5%, Case/Size Code=0402, Insulation Resistance=10GOhm, Manufacturer="Wurth Elektronik", Operating Temperature Max=125°C, Operating Temperature Min=-55°C, Rated Voltage (DC)=50V
C138_A1 C138_A2 C139_A1 C139_A2 C147_A1 C147_A2 C148_A1 C148_A2 C149_A1 C149_A2 C150_A1 C150_A2 C151_A1 C151_A2 C154_A1 C154_A2: library part CMP-0118819-1, "WCAP-CSGP Multilayer Ceramic Chip Capacitor, General Purpose, size 0402, NP0, 47pF, 50VDC", Capacitance Tolerance=+/-5%, Case/Size Code=0402, Insulation Resistance=10GOhm, Manufacturer="Wurth Elektronik", Operating Temperature Max=125°C, Operating Temperature Min=-55°C, Rated Voltage (DC)=50V
D1_A1 D1_A2: library part CMP-0084980-1, "Diode, TVS, Uni, 120 V, 193 Vc, 400 W, 2.1 A, SMA", Manufacturer=Littelfuse, Value1=193V
D2_A1 D2_A2: library part CMP-0123893-1, "11.5V Clamp 87A (8/20µs) Ipp Tvs Diode Surface Mount DO-219AD (MicroSMP)", Breakdown Voltage=4.1V, Clamping Voltage=11.5V, Digikey Part Number=MSP3V3-M3/89AGICT-ND, Manufacturer=Vishay, Mouser Part Number=625-MSP3V3-M3, Operating Temperature Range="-55°C to +150°C"
D3_A1 D3_A2: library part CMP-0086794-2, "DIODE SCHOTTKY 200V POWERDI123", Manufacturer=Diodes
D4_A1 D4_A2 D8_A1 D8_A2: library part CMP-0126010-1, "7.7V (Typ) Clamp 25A (8/20µs) Ipp Tvs Diode Surface Mount SOD-323", Breakdown Voltage=4.5V, Clamping Voltage=7.7V, Digikey Part Number=296-TSD03DYFRCT-ND, Manufacturer="Texas Instruments", Mouser Part Number=595-TSD03DYFR, Operating Temperature Range="-55°C to +150°C", ValueDisplayed=4.5pF
D5_A1 D5_A2 D6_A1 D6_A2: library part CMP-0120072-1, "2-Channel ESD Protection Diode", Manufacturer="Texas Instruments", Operating Temperature Range=to
D7_A1 D7_A2: library part CMP-0033054-1, "SMD16PL Series 60 V 1 A Surface Mount Schottky Rectifier - SOD-123FL", Digikey Part Number=SMD16PL-TPMSCT-ND, Forward Current=1A, Manufacturer="Micro Commercial Co", Max Surge Forward Current=30A, Mouser Part Number=833-SMD16PL-TP, Operating Temperature Range="-55°C to +125°C", Peak Reverse Current=0.1mA, ValueDisplayed=40pF
FID1 FID2 FID3: library part CMP-0077181-1, "Fiducial mark.  There is nothing to buy or mount.", Manufacturer=N/A
H1 H2 H3 H4: library part CMP-0078424-2, "PCB Mounting Hole, No Pad", Manufacturer=Any, PartNumber=N/A
J1 J2: library part CMP-0055239-1, "Header(shrouded), 2.54mm, 4x1, R/A, Gold, TH", Color=Black, Current_A=3A, Manufacturer=Molex, Supplier Part Number 1=0705510038-ND, Voltage_V=250V
J1_A1 J1_A2: library part CMP-1502-01086-4, "THT Vertical Pin Header WR-PHD, Pitch 2.54 mm, Single Row, 12 pins", Color=Black, Contact Resistance=20mΩ, Current Rating=3A, Operating Supply Voltage=250V
J2_A1 J2_A2 J3_A1 J3_A2: library part CMP-0054804-1, "Header, 2.54mm, 10x1, Gold, TH", Color=Black, Manufacturer="Wurth Elektronik", Supplier Part Number 1=732-2670-ND
J4_A1 J4_A2: library part CMP-0123118-1, "2.00mm Wafer, Right Angle Connector, 40pins, Key-A With CPA Feature", Current_A=3A, Manufacturer="BEIJIDA ELECTRONICS TECHNOLOGY", Operating Temperature Range="-40°C to +125°C", Voltage_V=60V
J5_A1 J5_A2: library part CMP-0123118-1, "2.00mm Wafer, Right Angle Connector, 40pins, Key-A With CPA Feature", Current_A=3A, Manufacturer="BEIJIDA ELECTRONICS TECHNOLOGY", Operating Temperature Range="-40°C to +125°C", Part Number=141114-214010, Voltage_V=60V
J6_A1 J6_A2 J9_A1 J9_A2 J10_A1 J10_A2: library part CMP-0002338-1, "Header, 100mil, 3x1, Tin, TH", Color=Black, Current_A=3A, Manufacturer="Sullins Connector Solutions", Supplier Part Number 1=S1012E-03-ND, Voltage_V=1.8kV
J7_A1 J7_A2: library part CMP-0075634-2, "Header(Shrouded), 1.27mm, 5x2, Gold, SMT", Color=Black, Current_A=3.3A, Manufacturer=Samtec, Supplier Part Number 1=SAM8799-ND
J8_A1 J8_A2: library part CMP-0054591-2, "Header, 2.54mm, 10x2, Gold, TH", Color=Black, Manufacturer="Sullins Connector Solutions", Supplier Part Number 1=S2011EC-10-ND
J11_A1 J11_A2: library part CMP-0080461-1, "Header(shrouded), 2mm, 2x1, Tin, TH", Color=Natural, Current_A=2A, Manufacturer="JST Manufacturing", Supplier Part Number 1=455-1704-ND, Voltage_V=100V
J12_A1 J12_A2: library part CMP-0097616-1, "Conn Unshrouded Header HDR 6 POS 1.27mm Solder ST SMD Automotive T/R", Current_A=3.4A, Digikey Part Number=SAM13919CT-ND, Manufacturer=Samtec, Mouser Part Number=200-FTSH10301FDVTR, Operating Temperature Range="-55°C to +125°C", Part Number=FTSH-103-01-F-DV-TR
j13: library part CMP-0089624-1, "0.250\" (6.35mm) Quick Connect Male  Solder Connector Non-Insulated", Current_A=20A, Digikey Part Number=A29938CT-ND, Manufacturer="TE Connectivity", Mouser Part Number=571-638241, Operating Temperature Range="-40°C to +105°C"
L2_A1 L2_A2: library part CMP-03913-61645204-1, "74404042101 WE-LQS SMD Power Inductor 100uH", Ambient Temperature Range High=85°C, Ambient Temperature Range Low=-40°C, Case/Package=Nonstandard, Current Rating=420mA, DC Resistance (DCR)=1.43Ω, Inductance=100µH, Inductance Tolerance=20%, Max Operating Temperature=125°C, Saturation Current=560mA, Self Resonant Frequency=8MHz, Test Frequency=100kHz
LBL1: library part CMP-0003625-1, "Thermal Transfer Printable Labels, 0.650\" W x 0.200\" H - 10,000 per roll", Manufacturer=Brady, Supplier Part Number 1=97C5133
Logo1: library part CMP-0074838-1, "Texas Instrument Corporate Signature"
Logo2: library part CMP-0074844-1
Logo3: library part CMP-0074847-1, "FCC_disclaimer"
Logo4: library part CMP-0074769-1
LOGO5: library part CMP-0074835-1, "IEC 61010-1 High Voltage Warning"
NFAULT_LED1_A1 NFAULT_LED1_A2: library part CMP-0002947-3, "LED, Red, SMD", Color=Red, Manufacturer="Wurth Elektronik", Power_TotalModule=72mW, Value1=0.072W, Value2=2V
Q1_A1 Q1_A2: library part CMP-0098136-1, "Trans MOSFET N/P-CH Si 20V 0.8A 6-Pin ES T/R", Digikey Part Number=264-SSM6L56FELMCT-ND, Drain To Source Breakdown Voltage=20V, Manufacturer="Toshiba Semiconductor and Storage", Mouser Part Number=757-SSM6L56FELM, Operating Temperature Range="to +150°C", Power_W=150mW, Pulse Drain Current=1600mA, Typ Forward Diode Voltage=-0.82/0.9V
R1_A1 R1_A2: library part CMP-0021100-3, "RES, 28.0, 1%, 0.125 W, AEC-Q200 Grade 0, 0805", Manufacturer=Vishay-Dale, Power_W=125mW, Supplier Part Number 1=541-28.0CCT-ND, TempCo="100 ppm/C", Tolerance_%=1%, Value2=0.125W, Value_Code=28R0, ValueDisplayed=28.0
R2_A1 R2_A2 R3_A1 R3_A2 R4_A1 R4_A2 R5_A1 R5_A2 R8_A1 R8_A2 R9_A1 R9_A2 R10_A1 R10_A2 R11_A1 R11_A2 R12_A1 R12_A2 R13_A1 R13_A2 R14_A1 R14_A2 R15_A1 R15_A2 R16_A1 R16_A2 R17_A1 R17_A2 R18_A1 R18_A2 R19_A1 R19_A2 R21_A1 R21_A2 R22_A1 R22_A2 R23_A1 R23_A2 R24_A1 R24_A2 R25_A1 R25_A2 R26_A1 R26_A2 R27_A1 R27_A2 R28_A1 R28_A2 R29_A1 R29_A2 R30_A1 R30_A2 R31_A1 R31_A2 R32_A1 R32_A2 R33_A1 R33_A2 R34_A1 R34_A2 R35_A1 R35_A2 R36_A1 R36_A2 R38_A1 R38_A2 R39_A1 R39_A2 R40_A1 R40_A2 R41_A1 R41_A2 R42_A1 R42_A2 R43_A1 R43_A2 R44_A1 R44_A2 R45_A1 R45_A2 R46_A1 R46_A2 R47_A1 R47_A2 R48_A1 R48_A2 R49_A1 R49_A2 R51_A1 R51_A2 R52_A1 R52_A2 R53_A1 R53_A2 R54_A1 R54_A2 R58_A1 R58_A2 R59_A1 R59_A2 R60_A1 R60_A2 R61_A1 R61_A2 R62_A1 R62_A2 R63_A1 R63_A2 R64_A1 R64_A2 R65_A1 R65_A2 R66_A1 R66_A2 R67_A1 R67_A2 R68_A1 R68_A2 R69_A1 R69_A2 R72_A1 R72_A2 R73_A1 R73_A2 R74_A1 R74_A2 R75_A1 R75_A2 R80_A1 R80_A2 R81_A1 R81_A2 R82_A1 R82_A2 R83_A1 R83_A2 R84_A1 R84_A2 R85_A1 R85_A2 R86_A1 R86_A2 R87_A1 R87_A2 R88_A1 R88_A2 R89_A1 R89_A2 R90_A1 R90_A2 R91_A1 R91_A2 R92_A1 R92_A2 R93_A1 R93_A2 R94_A1 R94_A2 R95_A1 R95_A2 R96_A1 R96_A2 R97_A1 R97_A2 R98_A1 R98_A2 R99_A1 R99_A2 R100_A1 R100_A2 R101_A1 R101_A2 R102_A1 R102_A2 R103_A1 R103_A2 R104_A1 R104_A2 R107_A1 R107_A2 R108_A1 R108_A2 R109_A1 R109_A2 R110_A1 R110_A2 R111_A1 R111_A2 R112_A1 R112_A2 R113_A1 R113_A2 R114_A1 R114_A2 R115_A1 R115_A2 R116_A1 R116_A2 R117_A1 R117_A2 R118_A1 R118_A2 R119_A1 R119_A2 R120_A1 R120_A2 R121_A1 R121_A2 R122_A1 R122_A2 R123_A1 R123_A2 R124_A1 R124_A2 R125_A1 R125_A2: library part CMP-0020585-3, "RES, 68, 5%, 0.125 W, AEC-Q200 Grade 0, 0805", Manufacturer=RESI, Power_W=125mW, Supplier Part Number 1=541-68ACT-ND, TempCo="200 ppm/C", Tolerance_%=5%, Value2=0.125W, Value_Code=68R0, ValueDisplayed=68
R6_A1 R6_A2: library part CMP-0127321-1, "RES Thick Film, 62Ω, 5%, 0.75W, 200ppm/°C, 1206", Manufacturer="Vishay Dale", Operating Temperature Range="-55°C to +155°C", Power_W=750mW, TempCo=200ppm/°C, Tolerance_%=5%
R7_A1 R7_A2: library part CMP-0020567-3, "RES, 51, 5%, 0.125 W, AEC-Q200 Grade 0, 0805", Manufacturer=Vishay-Dale, Power_W=125mW, Supplier Part Number 1=541-51ACT-ND, TempCo="200 ppm/C", Tolerance_%=5%, Value2=0.125W, Value_Code=51R0, ValueDisplayed=51
R20_A1 R20_A2: library part CMP-0025703-4, "RES, 10, 5%, 0.1 W, AEC-Q200 Grade 0, 0603", Manufacturer=Vishay-Dale, PartNumber=CRCW060310R0JNEA, Power_W=100mW, Supplier Part Number 1=541-10GCT-ND, TempCo="200 ppm/C", Tolerance_%=5%, Value2=0.1W, Value_Code=10R0, ValueDisplayed=10
R37_A1 R37_A2: library part CMP-0022769-5, "RES, 120, 1%, 0.1 W, 0603", Manufacturer=Yageo, Power_W=100mW, Supplier Part Number 1=311-120HRCT-ND, TempCo="100 ppm/C", Tolerance_%=1%, Value2=0.1W, Value_Code=120R, ValueDisplayed=120
R50_A1 R50_A2: library part CMP-0025874-4, "RES, 0, 5%, 0.1 W, AEC-Q200 Grade 0, 0603", Manufacturer=Panasonic, Power_W=100mW, Supplier Part Number 1=P0.0GCT-ND, TempCo="600 ppm/C", Tolerance_%=5%, Value2=0.1W, Value_Code=0000, ValueDisplayed=0
R55_A1 R55_A2 R57_A1 R57_A2: library part CMP-0088611-1, "Res Thick Film 0402 10 Ohm 1% 0.1W(1/10W) ±100ppm/C Molded SMD Automotive Punched T/R", Digikey Part Number=P10.0LCT-ND, Manufacturer=Panasonic, Mouser Part Number=667-ERJ-2RKF10R0X, Operating Temperature Range="-55°C to +155°C", Power_W=100mW, TempCo=100ppm/°C, Tolerance_%=1%
R56_A1 R56_A2 R76_A1 R76_A2: library part CMP-0025959-3, "RES, 10.2 k, 1%, 0.063 W, AEC-Q200 Grade 0, 0402", Manufacturer=Vishay-Dale, Power_W=63mW, Supplier Part Number 1=541-10.2KLCT-ND, TempCo="100 ppm/C", Tolerance_%=1%, Value2=0.063W, Value_Code=10k2, ValueDisplayed=10.2k
R70_A1 R70_A2 R71_A1 R71_A2 R77_A1 R77_A2 R78_A1 R78_A2 R79_A1 R79_A2 R105_A1 R105_A2 R209_A1 R209_A2 R211_A1 R211_A2 R226_A1 R226_A2 R227_A1 R227_A2: library part CMP-0026992-3, "RES, 0, 5%, 0.1 W, AEC-Q200 Grade 0, 0402", Manufacturer=Panasonic, Power_W=100mW, Supplier Part Number 1=P0.0JCT-ND, TempCo="600 ppm/C", Tolerance_%=5%, Value2=0.1W, Value_Code=0000, ValueDisplayed=0
R126_A1 R126_A2 R129_A1 R129_A2 R153_A1 R153_A2 R185_A1 R185_A2: library part CMP-0026739-1, "RES, 4.70 k, 1%, 0.0625 W, 0402", Manufacturer="Yageo America", Power_W=62.5mW, Supplier Part Number 1=311-4.7KLRCT-ND, TempCo="100 ppm/C", Tolerance_%=1%, Value2=0.0625W, Value_Code=4k70, ValueDisplayed=4.70k
R127_A1 R127_A2 R128_A1 R128_A2 R130_A1 R130_A2: library part CMP-0084244-1, "RES, 1.0 k, 5%, 0.25 W, AEC-Q200 Grade 0, 0603", Manufacturer=Rohm, Power_W=250mW, TempCo="200 ppm/C", Tolerance_%=5%, Value2=0.25W, Value_Code=1k00, ValueDisplayed=1.0k
R131_A1 R131_A2 R132_A1 R132_A2 R133_A1 R133_A2 R134_A1 R134_A2 R135_A1 R135_A2 R136_A1 R136_A2 R137_A1 R137_A2 R138_A1 R138_A2 R168_A1 R168_A2 R169_A1 R169_A2 R170_A1 R170_A2 R171_A1 R171_A2 R172_A1 R172_A2 R173_A1 R173_A2 R174_A1 R174_A2 R175_A1 R175_A2 R193_A1 R193_A2: library part CMP-0025958-3, "RES, 10.0 k, 1%, 0.063 W, AEC-Q200 Grade 0, 0402", Manufacturer=Vishay-Dale, Power_W=63mW, Supplier Part Number 1=541-10.0KLCT-ND, TempCo="100 ppm/C", Tolerance_%=1%, Value2=0.063W, Value_Code=10k0, ValueDisplayed=10.0k
R140_A1 R140_A2 R141_A1 R141_A2 R143_A1 R143_A2 R146_A1 R146_A2 R147_A1 R147_A2 R149_A1 R149_A2 R152_A1 R152_A2 R156_A1 R156_A2 R159_A1 R159_A2 R160_A1 R160_A2 R163_A1 R163_A2 R176_A1 R176_A2 R177_A1 R177_A2 R178_A1 R178_A2 R180_A1 R180_A2 R181_A1 R181_A2 R182_A1 R182_A2 R184_A1 R184_A2 R186_A1 R186_A2 R188_A1 R188_A2 R189_A1 R189_A2 R190_A1 R190_A2 R196_A1 R196_A2: library part CMP-0026852-3, "RES, 1.0 k, 5%, 0.063 W, AEC-Q200 Grade 0, 0402", Manufacturer=Vishay-Dale, Power_W=63mW, Supplier Part Number 1=541-1.0KJCT-ND, TempCo="200 ppm/C", Tolerance_%=5%, Value2=0.063W, Value_Code=1k00, ValueDisplayed=1.0k
R144_A1 R144_A2 R150_A1 R150_A2 R155_A1 R155_A2 R157_A1 R157_A2 R162_A1 R162_A2 R164_A1 R164_A2 R165_A1 R165_A2 R166_A1 R166_A2 R167_A1 R167_A2 R179_A1 R179_A2 R183_A1 R183_A2 R187_A1 R187_A2 R191_A1 R191_A2 R233_A1 R233_A2 R234_A1 R234_A2 R235_A1 R235_A2 R236_A1 R236_A2: library part CMP-0080661-1, "RES, 100 k, 1%, 0.0625 W, AEC-Q200 Grade 0, 0402", Manufacturer="Yageo America", Power_W=62.5mW, Supplier Part Number 1=YAG3434CT-ND, TempCo="100 ppm/C", Tolerance_%=1%, Value2=0.0625W, Value_Code=100k
R192_A1 R192_A2 R194_A1 R194_A2 R195_A1 R195_A2 R197_A1 R197_A2 R198_A1 R198_A2 R199_A1 R199_A2 R200_A1 R200_A2 R201_A1 R201_A2 R202_A1 R202_A2 R203_A1 R203_A2 R204_A1 R204_A2 R205_A1 R205_A2 R206_A1 R206_A2 R207_A1 R207_A2 R208_A1 R208_A2 R213_A1 R213_A2 R214_A1 R214_A2 R216_A1 R216_A2 R217_A1 R217_A2 R219_A1 R219_A2 R220_A1 R220_A2 R223_A1 R223_A2 R224_A1 R224_A2 R229_A1 R229_A2 R230_A1 R230_A2 R231_A1 R231_A2 R232_A1 R232_A2: library part CMP-0026071-3, "RES, 1.00 k, 1%, 0.063 W, AEC-Q200 Grade 0, 0402", Manufacturer=Vishay-Dale, Power_W=63mW, Supplier Part Number 1=541-1.00KLCT-ND, TempCo="100 ppm/C", Tolerance_%=1%, Value2=0.063W, Value_Code=1k00, ValueDisplayed=1.00k
R210_A1 R210_A2 R212_A1 R212_A2 R225_A1 R225_A2 R228_A1 R228_A2: library part CMP-0020617-3, "RES, 10, 5%, 0.125 W, AEC-Q200 Grade 0, 0805", Manufacturer=Panasonic, Power_W=125mW, Supplier Part Number 1=P10ACT-ND, TempCo="200 ppm/C", Tolerance_%=5%, Value2=0.125W, Value_Code=10R0, ValueDisplayed=10
R215_A1 R215_A2 R218_A1 R218_A2 R221_A1 R221_A2 R222_A1 R222_A2: library part CMP-0017732-3, "RES, 80.6, 1%, 0.25 W, AEC-Q200 Grade 0, 1206", Manufacturer=Panasonic, Power_W=250mW, Supplier Part Number 1=P80.6FCT-ND, TempCo="100 ppm/C", Tolerance_%=1%, Value2=0.25W, Value_Code=80R6, ValueDisplayed=80.6
RT1_A1 RT1_A2: library part CMP-0091865-2, "±1% tolerance 10kΩ linear thermistor available in 0402 and 0603 package options 2-SOT-5X3 -40 to 125", Digikey Part Number=296-TMP6131DYATCT-ND, Manufacturer="Texas Instruments", Max Current=400uA, Mouser Part Number=595-TMP6131DYAT, Operating Temperature Range="-40°C to +125°C", TempCo=6400ppm/°C, Tolerance_%=1%
T1 T3: library part CMP-0122349-1, "SMD BMS Transformer", Manufacturer="LineKey Technology", Operating Temperature Range="-40°C to +125°C", Voltage_Isolation_Vrms=5000VDC
T2: library part CMP-0086619-1, "BMS TRANSFORMER", Manufacturer="Wurth Elektronik"
U1_A1 U1_A2: library part CMP-0065574-3, "Automotive 26S/24S Battery Monitor with Smart EIS Engine", Manufacturer="Texas Instruments", Operating Temperature Range="-40°C to +125°C"
U2_A1 U2_A2 U3_A1 U3_A2: library part CMP-0090991-1, "5-V, 8: 1, 1-channel general-purpose multiplexer with 1.8-V logic control 16-TSSOP -40 to 125", Digikey Part Number=296-TMUX1308PWRCT-ND, Manufacturer="Texas Instruments", Max Supply Voltage=5.5V, Min Supply Voltage=1.62V, Mouser Part Number=595-TMUX1308PWR, Nominal Supply Current=1uA, On State Resistance=75-650Ω, Operating Temperature Range="-40°C to +125°C"
U4_A1 U4_A2: library part CMP-0065077-3, "Low-Dropout Regulator, DBV0005A (SOT-23-5)", Alternate Manufacturer="Texas Instruments"
U5_A1 U5_A2: library part CMP-0097640-1, "Dual-Supply Inverting Translator with Schmitt-Trigger Input", Digikey Part Number=296-SN74LXC1T14DCKRCT-ND, Manufacturer="Texas Instruments", Mouser Part Number=595-SN74LXC1T14DCKR, Nominal Supply Current=3uA, Operating Temperature Range="-40°C to +125°C"
Y2_A1 Y2_A2: library part CMP-0122977-1, "8 MHz ±20ppm Crystal 18pF 150 Ohms 4-SMD, No Lead", Digikey Part Number=1923-830055663CT-ND, Frequency Stability=30ppm, Frequency Tolerance=20ppm, Frequency_Fixed=8MHz, Load Capacitance=18pF, Manufacturer=Wurth, Mouser Part Number=710-830055663, Operating Temperature Range="-40°C to +85°C"
ZZ1: library part CMP-0003616-3
ZZ2: library part CMP-0077236-1
ZZ3: library part CMP-0077237-1
ZZ4: library part CMP-0077238-1

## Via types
v1: diameter 0.559, hole 0.305, Top Layer to Bottom Layer, tented both sides, 1735 vias
v2: diameter 0.47, hole 0.2, Top Layer to Bottom Layer, tented both sides, 269 vias
v3: diameter 0.5, hole 0.2, Top Layer to Bottom Layer, tented both sides, 128 vias

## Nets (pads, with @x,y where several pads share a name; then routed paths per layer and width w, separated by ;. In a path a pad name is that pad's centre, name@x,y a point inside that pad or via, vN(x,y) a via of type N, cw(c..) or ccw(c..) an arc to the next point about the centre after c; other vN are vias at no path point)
AVDD_A1: C21_A1.2 C67_A1.1 C88_A1.1 J6_A1.1 R128_A1.1 U1_A1.88 U2_A1.16 U3_A1.16 | length 83.2
  Top Layer w0.178: v1@50.167,4.2 50.199,4.231 71.757,4.231 73.424,5.899 73.764,5.899 73.812,5.851 74.255,5.851 74.302,5.899 ; C88_A1.1@53.703,24.373 53.803,24.373 54.014,24.162 54.014,23.846 54.065,23.795 54.065,23.776 54.518,23.324 U3_A1.16@54.772,23.324 ; v2(54.772,23.801) U3_A1.16@54.772,23.324 ; U3_A1.16@55.043,23.324 U3_A1.16@54.772,23.324 ; C21_A1.2@73.142,14.365 73.142,14.34 72.378,13.576 72.378,11.892 72.491,11.779 73.895,11.779 74.573,11.101 74.573,6.169 74.302,5.899 ; C21_A1.2@73.142,14.39 73.528,14.776 73.78,15.028 73.78,15.032 74.554,15.806 74.768,15.806 75.657,16.695 U1_A1.88@75.657,17.774 ; v2(77.553,5.096) 77.537,5.111 74.791,5.111 74.302,5.6 74.302,5.899
  Mid Layer 1 w0.178: J6_A1.1@47.323,15.501 45.529,13.707 45.529,5.682 46.573,4.638 46.573,4.58 47.039,4.114 47.826,4.114 47.943,4.231 v1(50.12,4.231)
  Bottom Layer w0.178: U2_A1.16@54.473,18.539 U2_A1.16@54.483,18.549 ; v2(77.553,5.096) 77.598,5.141 77.598,5.48 77.871,5.753 78.447,5.753 78.833,6.139 R128_A1.1@78.833,6.164
  Bottom Layer w0.254: 55.297,18.549 55.741,18.106 56.691,18.106 57.005,18.421 57.005,19.369 57.163,19.527 57.163,20.618 57.095,20.686 57.095,23.801
  Bottom Layer w0.305: J6_A1.1@47.323,15.501 48.47,16.648 51.468,16.648 51.871,17.051 51.871,17.141 52.071,17.341 52.071,17.349 52.218,17.497 52.418,17.497 53.475,18.554 54.458,18.554 U2_A1.16@54.473,18.539 ; U2_A1.16@54.483,18.549 55.297,18.549 ; v2(54.772,23.801) 57.095,23.801
AVDD_A2: C21_A2.2 C67_A2.1 C88_A2.1 J6_A2.1 R128_A2.1 U1_A2.88 U2_A2.16 U3_A2.16 | length 83.3
  Top Layer w0.178: v1@155.167,4.25 155.199,4.281 176.757,4.281 178.424,5.949 178.764,5.949 178.812,5.901 179.255,5.901 179.302,5.949 ; C88_A2.1@158.703,24.423 158.803,24.423 159.014,24.212 159.014,23.896 159.065,23.845 159.065,23.826 159.518,23.374 U3_A2.16@159.772,23.374 ; v2(159.772,23.851) U3_A2.16@159.772,23.374 ; U3_A2.16@160.043,23.374 U3_A2.16@159.772,23.374 ; C21_A2.2@178.142,14.415 178.142,14.39 177.378,13.626 177.378,11.942 177.491,11.829 178.895,11.829 179.573,11.151 179.573,6.219 179.302,5.949 ; C21_A2.2@178.142,14.44 178.528,14.826 178.78,15.078 178.78,15.082 179.554,15.856 179.768,15.856 180.657,16.745 U1_A2.88@180.657,17.824 ; v2(182.553,5.146) 182.537,5.161 179.791,5.161 179.302,5.65 179.302,5.949
  Mid Layer 1 w0.178: J6_A2.1@152.323,15.551 150.529,13.757 150.529,5.732 151.573,4.688 151.573,4.63 152.039,4.164 152.826,4.164 152.943,4.281 v1(155.12,4.281)
  Bottom Layer w0.178: U2_A2.16@159.473,18.589 U2_A2.16@159.483,18.599 ; v2(182.553,5.146) 182.598,5.191 182.598,5.53 182.871,5.803 183.447,5.803 183.833,6.189 R128_A2.1@183.833,6.214
  Bottom Layer w0.254: 160.297,18.599 160.741,18.156 161.839,18.156 162.023,18.34 162.023,19.066 162.181,19.224 162.181,20.664 162.095,20.75 162.095,23.851
  Bottom Layer w0.305: J6_A2.1@152.323,15.551 153.47,16.698 156.468,16.698 156.871,17.101 156.871,17.191 157.071,17.391 157.071,17.399 157.218,17.547 157.418,17.547 158.475,18.604 159.458,18.604 U2_A2.16@159.473,18.589 ; U2_A2.16@159.483,18.599 160.297,18.599 ; v2(159.772,23.851) 162.095,23.851
BAT_A1: C9_A1.2 C41_A1.2 C122_A1.2 D2_A1.1 R1_A1.1 U1_A1.6 | length 18.4
  Top Layer w0.178: C9_A1.2@84.393,19.814 84.393,19.789 83.879,19.274 83.697,19.274 83.682,19.26 81.517,19.26 81.318,19.458 81.318,21.439 81.517,21.637 82.321,21.637 U1_A1.6@82.332,21.649 v1(83.897,21.649) 85.376,21.649 C122_A1.2@85.441,21.713 87.484,21.713 87.688,21.917 87.818,21.917 87.818,22.011 88.626,22.819 R1_A1.1@88.626,22.984 ; R1_A1.1@88.64,22.903 R1_A1.1@89.186,22.357 ; D2_A1.1@89.282,21.045 89.186,21.141 89.186,21.535 R1_A1.1@89.186,22.357 ; R1_A1.1@88.626,22.917 R1_A1.1@88.626,22.984 ; R1_A1.1@88.626,22.917 R1_A1.1@89.186,22.357 ; R1_A1.1@88.626,22.917 R1_A1.1@88.626,22.984 ; R1_A1.1@88.626,22.917 R1_A1.1@89.186,22.357
  Bottom Layer w0.178: v1(83.897,21.649) 84,21.649 84.306,21.954 84.683,21.954 C41_A1.2@84.775,21.863
BAT_A2: C9_A2.2 C41_A2.2 C122_A2.2 D2_A2.1 R1_A2.1 U1_A2.6 | length 18.8
  Top Layer w0.178: C9_A2.2@189.393,19.864 189.393,19.839 188.879,19.324 188.697,19.324 188.682,19.31 186.517,19.31 186.318,19.508 186.318,21.489 186.517,21.687 187.321,21.687 U1_A2.6@187.332,21.699 v1(188.897,21.699) 190.376,21.699 C122_A2.2@190.441,21.763 192.484,21.763 192.688,21.967 192.724,21.967 R1_A2.1@193.626,22.869 ; D2_A2.1@194.186,21.234 194.271,21.32 194.081,21.51 194.294,21.297 D2_A2.1@194.294,21.08 ; D2_A2.1@194.186,21.32 R1_A2.1@194.186,22.407 ; R1_A2.1@193.626,22.967 R1_A2.1@193.626,23.034 R1_A2.1@193.626,22.967 ; R1_A2.1@193.626,22.967 R1_A2.1@194.186,22.407 ; R1_A2.1@193.626,22.967 R1_A2.1@193.675,22.918 ; R1_A2.1@193.626,22.967 R1_A2.1@193.675,22.918 ; R1_A2.1@193.675,22.918 R1_A2.1@194.186,22.407 ; R1_A2.1@193.675,22.918 R1_A2.1@194.186,22.407
  Bottom Layer w0.178: v1(188.897,21.699) 189,21.699 189.306,22.004 189.683,22.004 C41_A2.2@189.775,21.913
BATPWR_A1: C19_A1.2 D2_A1.2 R7_A1.2 U1_A1.5 | length 11.7
  Top Layer w0.178: U1_A1.5@82.332,21.249 83.466,21.249 83.635,21.08 84.291,21.08
  Top Layer w0.203: 84.291,21.08 85.698,21.08 85.817,20.961 85.817,20.727 86.191,20.353 C19_A1.2@86.559,20.353 86.559,19.969 87.093,19.436
  Top Layer w0.381: 87.093,19.436 88.481,19.436 88.744,19.174 90.26,19.174 R7_A1.2@90.342,19.092 90.597,19.346 90.597,19.38 91.367,20.15 91.367,20.86 D2_A1.2@91.182,21.045
BATPWR_A2: C19_A2.2 D2_A2.2 R7_A2.2 U1_A2.5 | length 11.6
  Top Layer w0.178: U1_A2.5@187.332,21.299 188.466,21.299 188.635,21.13 189.291,21.13
  Top Layer w0.203: 189.291,21.13 190.698,21.13 190.817,21.011 190.817,20.777 191.191,20.403 C19_A2.2@191.559,20.403 191.559,20.019 192.093,19.486
  Top Layer w0.381: 192.093,19.486 193.481,19.486 193.744,19.224 195.26,19.224 R7_A2.2@195.342,19.142 195.342,19.307 195.787,19.751 195.805,19.751 196.028,19.974 196.028,20.914 D2_A2.2@196.194,21.08
BMU_COMMH_N: J2.4 T3.1 | length 13.7
  Top Layer w0.254: 236.796,69.907 236.796,70.672 235.865,71.603 235.865,79.88 237.175,81.19 237.461,81.19 238.071,81.8 J2.4@238.435,81.8
BMU_COMMH_P: J2.3 T3.3 | length 13.5
  Top Layer w0.254: 231.716,69.907 231.716,70.61 T3.3@232.011,70.905 ; T3.3@231.716,71.2 231.716,71.965 235.27,75.519 235.27,80.811 235.895,81.436 J2.3@235.895,81.8
BMU_COMML_P: J1.2 T1.1 | length 12.3
  Top Layer w0.254: J1.2@7.96,81.81 7.96,81.782 8.781,80.961 8.781,74.459 T1.1@12.04,71.2
BMU_OMML_N: J1.1 T1.3 | length 12.7
  Top Layer w0.254: J1.1@5.42,81.81 6.601,81.81 6.833,81.578 6.833,77.787 7.875,76.745 7.875,72.115 T1.3@6.96,71.2
BTSP_A1: C31_A1.2 U1_A1.100 | length 1.7
  Top Layer w0.178: U1_A1.100@80.457,17.774 80.457,17.151 80.468,17.14 81.436,17.14 C31_A1.2@81.484,17.092
BTSP_A2: C31_A2.2 U1_A2.100 | length 1.7
  Top Layer w0.178: U1_A2.100@185.457,17.824 185.457,17.201 185.468,17.19 186.436,17.19 C31_A2.2@186.484,17.142
CB0_A1: C53_A1.1 C58_A1.2 D4_A1.1 R122_A1.2 R123_A1.2 R124_A1.2 R125_A1.2 U1_A1.62 | length 50.3
  Top Layer w0.178: U1_A1.62@68.982,24.849 68.987,24.844 70.066,24.844 v1(70.071,24.838)
  Bottom Layer w0.305: v1(34.175,42.038) 34.14,42.003 34.14,39.637 34.877,38.9 42.974,38.9 44.108,37.766 50.491,37.766 52.005,36.252 58.183,36.252 59.665,34.769 61.234,34.769 61.73,34.273 61.73,31.682 61.651,31.603 61.651,29.296 61.73,29.217 61.73,27.614 63.087,26.258 63.087,25.907 ; D4_A1.1@62.822,25.914 62.958,25.778 63.087,25.907 ; C53_A1.1@64.272,25.493 C53_A1.1@64.222,25.493 ; v1(70.071,24.838) 68.846,24.838 68.787,24.779 66.004,24.779 65.607,25.176 65.607,25.258 65.428,25.436 65.155,25.436 65.098,25.493 C53_A1.1@64.222,25.493 ; 63.087,25.907 63.438,25.907 63.804,25.541 64.175,25.541 C53_A1.1@64.222,25.493
  other v1: 34.175,42.881 34.175,43.724 34.175,44.567 34.175,45.41 34.175,46.253 34.175,47.096
CB0_A2: C53_A2.1 C58_A2.2 D4_A2.1 R122_A2.2 R123_A2.2 R124_A2.2 R125_A2.2 U1_A2.62 | length 50.3
  Top Layer w0.178: U1_A2.62@173.982,24.899 173.987,24.894 175.066,24.894 v1(175.071,24.888)
  Bottom Layer w0.305: v1(139.175,42.088) 139.14,42.053 139.14,39.687 139.877,38.95 147.974,38.95 149.108,37.816 155.491,37.816 157.005,36.302 163.183,36.302 164.665,34.819 166.234,34.819 166.73,34.323 166.73,31.732 166.651,31.653 166.651,29.346 166.73,29.267 166.73,27.664 168.087,26.308 168.087,25.957 ; D4_A2.1@167.822,25.964 167.958,25.828 168.087,25.957 ; C53_A2.1@169.272,25.543 C53_A2.1@169.222,25.543 ; v1(175.071,24.888) 173.846,24.888 173.787,24.829 171.004,24.829 170.607,25.226 170.607,25.308 170.428,25.486 170.155,25.486 170.098,25.543 C53_A2.1@169.222,25.543 ; 168.087,25.957 168.438,25.957 168.804,25.591 169.175,25.591 C53_A2.1@169.222,25.543
  other v1: 139.175,42.931 139.175,43.774 139.175,44.617 139.175,45.46 139.175,46.303 139.175,47.146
